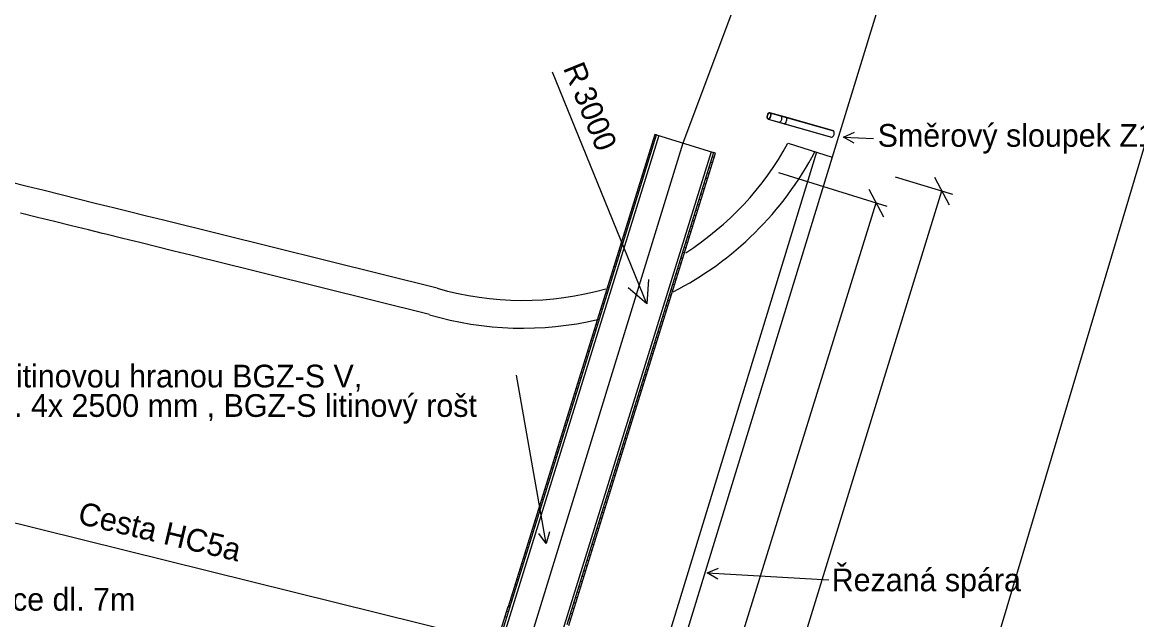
# Model space of a CAD drawing. Extents: x -577013.5 to -576971.5, y -1164310.3 to -1164280.6.
# Drawn here: x -576998.03 to -576987.9, y -1164293.5 to -1164288.07 of the extents above; entities that cross this region are included whole.
import ezdxf

# ---------------------------------------------------------------- set-up
doc = ezdxf.new("R2010")
doc.units = 0
for name, color, linetype in [('37', 7, 'Continuous'), ('5', 7, 'Continuous'), ('60', 7, 'Continuous'), ('Směrové sloupky detail', 7, 'Continuous'), ('Vrstva 1', 7, 'Continuous'), ('Žlab', 7, 'Continuous')]:
    doc.layers.add(name, color=color, linetype=linetype)

msp = doc.modelspace()

# ---------------------------------------------------------------- linework, layer by layer
for p, q in [((-576992.351, -1164290.63), (-576993.207, -1164288.52)), ((-576991.067, -1164289.167), (-576990.666, -1164289.295)), ((-576997.983, -1164289.561), (-576998.138, -1164289.523)), ((-576991.154, -1164289.435), (-576990.17, -1164289.74)), ((-576990.092, -1164289.472), (-576989.572, -1164289.632)), ((-576989.734, -1164289.477), (-576989.602, -1164289.727)), ((-576997.828, -1164289.599), (-576997.983, -1164289.561)), ((-576997.673, -1164289.638), (-576997.828, -1164289.599)), ((-576992.94, -1164300.242), (-576989.668, -1164289.602)), ((-576990.331, -1164289.585), (-576990.199, -1164289.836)), ((-576997.519, -1164289.676), (-576997.673, -1164289.638)), ((-576997.364, -1164289.715), (-576997.519, -1164289.676)), ((-576997.238, -1164289.746), (-576997.364, -1164289.715)), ((-576993.228, -1164299.263), (-576990.265, -1164289.711)), ((-576997.888, -1164289.842), (-576998.043, -1164289.804)), ((-576997.209, -1164289.753), (-576997.238, -1164289.746)), ((-576997.054, -1164289.791), (-576997.209, -1164289.753)), ((-576996.899, -1164289.83), (-576997.054, -1164289.791)), ((-576996.744, -1164289.868), (-576996.899, -1164289.83)), ((-576997.733, -1164289.88), (-576997.888, -1164289.842)), ((-576997.579, -1164289.919), (-576997.733, -1164289.88)), ((-576997.424, -1164289.957), (-576997.579, -1164289.919)), ((-576994.255, -1164290.486), (-576996.744, -1164289.868)), ((-576997.298, -1164289.988), (-576997.424, -1164289.957)), ((-576997.269, -1164289.996), (-576997.298, -1164289.988)), ((-576997.114, -1164290.034), (-576997.269, -1164289.996)), ((-576996.959, -1164290.072), (-576997.114, -1164290.034)), ((-576996.804, -1164290.111), (-576996.959, -1164290.072)), ((-576996.65, -1164290.149), (-576996.804, -1164290.111)), ((-576996.495, -1164290.187), (-576996.65, -1164290.149)), ((-576996.34, -1164290.226), (-576996.495, -1164290.187)), ((-576996.327, -1164290.229), (-576996.34, -1164290.226)), ((-576994.326, -1164290.727), (-576996.327, -1164290.229))]:
    msp.add_line(p, q)
msp.add_lwpolyline([(-576992.334, -1164290.407), (-576992.351, -1164290.63), (-576992.519, -1164290.482)])
for radius, start, end in [(2.748, 302.6493, 331.3573), (3, 297.1177, 332.2826), (2.748, 253.5888, 285.9607), (3, 253.5888, 283.1274)]:
    msp.add_arc((-576993.479, -1164287.85), radius, start, end)
at = {"layer": '37'}
for p, q in [((-576988.545, -1164282.361), (-576990.666, -1164289.295)), ((-576990.807, -1164289.25), (-576994.063, -1164299.897)), ((-576990.666, -1164289.295), (-576993.922, -1164299.942))]:
    msp.add_line(p, q, dxfattribs=at)
at = {"layer": '5'}
msp.add_line((-576992.135, -1164294.101), (-577005.054, -1164290.899), dxfattribs=at)
at = {"layer": '60'}
msp.add_line((-576989.475, -1164282.361), (-576992.024, -1164289.166), dxfattribs=at)
at = {"layer": 'Směrové sloupky detail'}
for p, q in [((-576991.232, -1164288.891), (-576990.654, -1164289.055)), ((-576991.248, -1164288.948), (-576990.671, -1164289.112))]:
    msp.add_line(p, q, dxfattribs=at)
for points in [[(-576991.131, -1164288.919), (-576991.232, -1164288.891)], [(-576991.232, -1164288.891), (-576991.232, -1164288.891)], [(-576991.248, -1164288.948), (-576991.147, -1164288.977), (-576991.147, -1164288.977)], [(-576991.248, -1164288.948), (-576991.248, -1164288.948)], [(-576991.147, -1164288.977), (-576991.104, -1164288.989)], [(-576991.087, -1164288.932), (-576991.087, -1164288.932), (-576991.131, -1164288.919)], [(-576991.104, -1164288.989), (-576990.671, -1164289.112)], [(-576990.654, -1164289.055), (-576991.087, -1164288.932)]]:
    msp.add_lwpolyline(points, dxfattribs=at)
for centre, start_param, end_param in [((-576991.24, -1164288.919), 0, 3.141593), ((-576991.24, -1164288.919), 3.141603, 6.283175), ((-576991.24, -1164288.919), 3.141603, 6.283175), ((-576991.139, -1164288.948), 3.141603, 6.283185), ((-576991.139, -1164288.948), 3.141603, 6.283175), ((-576991.095, -1164288.961), 3.141603, 6.283175), ((-576991.095, -1164288.961), 3.141593, 6.283175), ((-576990.663, -1164289.084), 3.141593, 6.283185)]:
    msp.add_ellipse(centre, major_axis=(0.0082, 0.0289), ratio=0.5, start_param=start_param, end_param=end_param, dxfattribs=at)
msp.add_ellipse((-576991.24, -1164288.919), major_axis=(0.0082, 0.0289), ratio=0.5, dxfattribs=at)
at = {"layer": 'Vrstva 1'}
for p, q in [((-576992.834, -1164306.008), (-576986.608, -1164285.099)), ((-576990.564, -1164289.113), (-576990.289, -1164289.125)), ((-576993.266, -1164292.809), (-576993.534, -1164291.278)), ((-576991.803, -1164293.077), (-576990.697, -1164293.139))]:
    msp.add_line(p, q, dxfattribs=at)
for points in [[(-576990.467, -1164289.167), (-576990.564, -1164289.113), (-576990.462, -1164289.067)], [(-576993.234, -1164292.702), (-576993.266, -1164292.809), (-576993.332, -1164292.719)], [(-576991.706, -1164293.132), (-576991.803, -1164293.077), (-576991.7, -1164293.033)]]:
    msp.add_lwpolyline(points, dxfattribs=at)
at = {"layer": 'Žlab'}
for p, q in [((-576992.242, -1164289.098), (-576995.204, -1164298.649)), ((-576992.279, -1164289.087), (-576992.279, -1164289.087)), ((-576992.263, -1164289.092), (-576991.744, -1164289.253)), ((-576992.024, -1164289.166), (-576994.962, -1164298.726)), ((-576992.306, -1164289.174), (-576992.289, -1164289.177)), ((-576992.291, -1164289.126), (-576992.274, -1164289.129)), ((-576991.764, -1164289.246), (-576994.727, -1164298.797)), ((-576992.351, -1164289.319), (-576992.334, -1164289.322)), ((-576992.336, -1164289.271), (-576992.319, -1164289.274)), ((-576992.321, -1164289.223), (-576992.304, -1164289.225)), ((-576991.756, -1164289.292), (-576991.738, -1164289.294)), ((-576991.744, -1164289.253), (-576991.744, -1164289.253)), ((-576992.381, -1164289.416), (-576992.364, -1164289.418)), ((-576992.366, -1164289.367), (-576992.349, -1164289.37)), ((-576991.786, -1164289.388), (-576991.768, -1164289.391)), ((-576991.771, -1164289.34), (-576991.753, -1164289.343)), ((-576992.411, -1164289.512), (-576992.394, -1164289.515)), ((-576992.396, -1164289.464), (-576992.379, -1164289.467)), ((-576991.815, -1164289.485), (-576991.798, -1164289.487)), ((-576991.801, -1164289.436), (-576991.783, -1164289.439)), ((-576992.441, -1164289.609), (-576992.424, -1164289.611)), ((-576992.426, -1164289.56), (-576992.409, -1164289.563)), ((-576991.845, -1164289.581), (-576991.828, -1164289.584)), ((-576991.83, -1164289.533), (-576991.813, -1164289.536)), ((-576992.471, -1164289.705), (-576992.454, -1164289.708)), ((-576992.456, -1164289.657), (-576992.439, -1164289.66)), ((-576991.89, -1164289.726), (-576991.873, -1164289.729)), ((-576991.875, -1164289.678), (-576991.858, -1164289.68)), ((-576991.86, -1164289.629), (-576991.843, -1164289.632)), ((-576992.501, -1164289.802), (-576992.484, -1164289.804)), ((-576992.486, -1164289.754), (-576992.469, -1164289.756)), ((-576991.92, -1164289.822), (-576991.903, -1164289.825)), ((-576991.905, -1164289.774), (-576991.888, -1164289.777)), ((-576992.531, -1164289.898), (-576992.514, -1164289.901)), ((-576992.516, -1164289.85), (-576992.499, -1164289.853)), ((-576991.95, -1164289.919), (-576991.933, -1164289.922)), ((-576991.935, -1164289.871), (-576991.918, -1164289.873)), ((-576992.561, -1164289.995), (-576992.544, -1164289.998)), ((-576992.546, -1164289.947), (-576992.529, -1164289.949)), ((-576991.98, -1164290.016), (-576991.963, -1164290.018)), ((-576991.965, -1164289.967), (-576991.948, -1164289.97)), ((-576992.591, -1164290.091), (-576992.574, -1164290.094)), ((-576992.576, -1164290.043), (-576992.559, -1164290.046)), ((-576992.01, -1164290.112), (-576991.993, -1164290.115)), ((-576991.995, -1164290.064), (-576991.978, -1164290.067)), ((-576992.621, -1164290.188), (-576992.603, -1164290.191)), ((-576992.606, -1164290.14), (-576992.589, -1164290.142)), ((-576992.04, -1164290.209), (-576992.023, -1164290.211)), ((-576992.025, -1164290.16), (-576992.008, -1164290.163)), ((-576992.666, -1164290.333), (-576992.648, -1164290.335)), ((-576992.651, -1164290.284), (-576992.633, -1164290.287)), ((-576992.636, -1164290.236), (-576992.618, -1164290.239)), ((-576992.07, -1164290.305), (-576992.053, -1164290.308)), ((-576992.055, -1164290.257), (-576992.038, -1164290.26)), ((-576992.696, -1164290.429), (-576992.678, -1164290.432)), ((-576992.681, -1164290.381), (-576992.663, -1164290.384)), ((-576992.1, -1164290.402), (-576992.083, -1164290.404)), ((-576992.085, -1164290.353), (-576992.068, -1164290.356)), ((-576992.726, -1164290.526), (-576992.708, -1164290.529)), ((-576992.711, -1164290.478), (-576992.693, -1164290.48)), ((-576992.13, -1164290.498), (-576992.112, -1164290.501)), ((-576992.115, -1164290.45), (-576992.098, -1164290.453)), ((-576992.756, -1164290.622), (-576992.738, -1164290.625)), ((-576992.741, -1164290.574), (-576992.723, -1164290.577)), ((-576992.16, -1164290.595), (-576992.142, -1164290.597)), ((-576992.145, -1164290.547), (-576992.127, -1164290.549)), ((-576992.786, -1164290.719), (-576992.768, -1164290.722)), ((-576992.771, -1164290.671), (-576992.753, -1164290.673)), ((-576992.205, -1164290.74), (-576992.187, -1164290.742)), ((-576992.19, -1164290.691), (-576992.172, -1164290.694)), ((-576992.175, -1164290.643), (-576992.157, -1164290.646)), ((-576992.815, -1164290.815), (-576992.798, -1164290.818)), ((-576992.801, -1164290.767), (-576992.783, -1164290.77)), ((-576992.235, -1164290.836), (-576992.217, -1164290.839)), ((-576992.22, -1164290.788), (-576992.202, -1164290.791)), ((-576992.845, -1164290.912), (-576992.828, -1164290.915)), ((-576992.83, -1164290.864), (-576992.813, -1164290.866)), ((-576992.265, -1164290.933), (-576992.247, -1164290.935)), ((-576992.25, -1164290.884), (-576992.232, -1164290.887)), ((-576992.875, -1164291.008), (-576992.858, -1164291.011)), ((-576992.86, -1164290.96), (-576992.843, -1164290.963)), ((-576992.295, -1164291.029), (-576992.277, -1164291.032)), ((-576992.28, -1164290.981), (-576992.262, -1164290.984)), ((-576992.905, -1164291.105), (-576992.888, -1164291.108)), ((-576992.89, -1164291.057), (-576992.873, -1164291.059)), ((-576992.324, -1164291.126), (-576992.307, -1164291.128)), ((-576992.31, -1164291.077), (-576992.292, -1164291.08)), ((-576992.935, -1164291.202), (-576992.918, -1164291.204)), ((-576992.92, -1164291.153), (-576992.903, -1164291.156)), ((-576992.354, -1164291.222), (-576992.337, -1164291.225)), ((-576992.339, -1164291.174), (-576992.322, -1164291.177)), ((-576992.98, -1164291.346), (-576992.963, -1164291.349)), ((-576992.965, -1164291.298), (-576992.948, -1164291.301)), ((-576992.95, -1164291.25), (-576992.933, -1164291.253)), ((-576992.384, -1164291.319), (-576992.367, -1164291.321)), ((-576992.369, -1164291.271), (-576992.352, -1164291.273)), ((-576993.01, -1164291.443), (-576992.993, -1164291.446)), ((-576992.995, -1164291.395), (-576992.978, -1164291.397)), ((-576992.414, -1164291.415), (-576992.397, -1164291.418)), ((-576992.399, -1164291.367), (-576992.382, -1164291.37)), ((-576993.04, -1164291.539), (-576993.023, -1164291.542)), ((-576993.025, -1164291.491), (-576993.008, -1164291.494)), ((-576992.444, -1164291.512), (-576992.427, -1164291.515)), ((-576992.429, -1164291.464), (-576992.412, -1164291.466)), ((-576993.07, -1164291.636), (-576993.053, -1164291.639)), ((-576993.055, -1164291.588), (-576993.038, -1164291.59)), ((-576992.474, -1164291.608), (-576992.457, -1164291.611)), ((-576992.459, -1164291.56), (-576992.442, -1164291.563)), ((-576993.1, -1164291.732), (-576993.083, -1164291.735)), ((-576993.085, -1164291.684), (-576993.068, -1164291.687)), ((-576992.519, -1164291.753), (-576992.502, -1164291.756)), ((-576992.504, -1164291.705), (-576992.487, -1164291.708)), ((-576992.489, -1164291.657), (-576992.472, -1164291.659)), ((-576993.13, -1164291.829), (-576993.112, -1164291.832)), ((-576993.115, -1164291.781), (-576993.098, -1164291.783)), ((-576992.549, -1164291.85), (-576992.532, -1164291.852)), ((-576992.534, -1164291.801), (-576992.517, -1164291.804)), ((-576993.16, -1164291.926), (-576993.142, -1164291.928)), ((-576993.145, -1164291.877), (-576993.127, -1164291.88)), ((-576992.579, -1164291.946), (-576992.562, -1164291.949)), ((-576992.564, -1164291.898), (-576992.547, -1164291.901)), ((-576993.19, -1164292.022), (-576993.172, -1164292.025)), ((-576993.175, -1164291.974), (-576993.157, -1164291.977)), ((-576992.609, -1164292.043), (-576992.592, -1164292.045)), ((-576992.594, -1164291.995), (-576992.577, -1164291.997)), ((-576993.22, -1164292.119), (-576993.202, -1164292.121)), ((-576993.205, -1164292.07), (-576993.187, -1164292.073)), ((-576992.639, -1164292.139), (-576992.622, -1164292.142)), ((-576992.624, -1164292.091), (-576992.607, -1164292.094)), ((-576993.25, -1164292.215), (-576993.232, -1164292.218)), ((-576993.235, -1164292.167), (-576993.217, -1164292.17)), ((-576992.669, -1164292.236), (-576992.651, -1164292.239)), ((-576992.654, -1164292.188), (-576992.636, -1164292.19)), ((-576993.295, -1164292.36), (-576993.277, -1164292.363)), ((-576993.28, -1164292.312), (-576993.262, -1164292.314)), ((-576993.265, -1164292.263), (-576993.247, -1164292.266)), ((-576992.699, -1164292.332), (-576992.681, -1164292.335)), ((-576992.684, -1164292.284), (-576992.666, -1164292.287)), ((-576993.324, -1164292.457), (-576993.307, -1164292.459)), ((-576993.31, -1164292.408), (-576993.292, -1164292.411)), ((-576992.729, -1164292.429), (-576992.711, -1164292.432)), ((-576992.714, -1164292.381), (-576992.696, -1164292.383)), ((-576993.354, -1164292.553), (-576993.337, -1164292.556)), ((-576993.339, -1164292.505), (-576993.322, -1164292.507)), ((-576992.759, -1164292.525), (-576992.741, -1164292.528)), ((-576992.744, -1164292.477), (-576992.726, -1164292.48)), ((-576993.384, -1164292.65), (-576993.367, -1164292.652)), ((-576993.369, -1164292.601), (-576993.352, -1164292.604)), ((-576992.789, -1164292.622), (-576992.771, -1164292.625)), ((-576992.774, -1164292.574), (-576992.756, -1164292.576)), ((-576993.414, -1164292.746), (-576993.397, -1164292.749)), ((-576993.399, -1164292.698), (-576993.382, -1164292.701)), ((-576992.834, -1164292.767), (-576992.816, -1164292.77)), ((-576992.819, -1164292.719), (-576992.801, -1164292.721)), ((-576992.804, -1164292.67), (-576992.786, -1164292.673)), ((-576993.444, -1164292.843), (-576993.427, -1164292.845)), ((-576993.429, -1164292.794), (-576993.412, -1164292.797)), ((-576992.863, -1164292.863), (-576992.846, -1164292.866)), ((-576992.848, -1164292.815), (-576992.831, -1164292.818)), ((-576993.474, -1164292.939), (-576993.457, -1164292.942)), ((-576993.459, -1164292.891), (-576993.442, -1164292.894)), ((-576992.893, -1164292.96), (-576992.876, -1164292.963)), ((-576992.878, -1164292.912), (-576992.861, -1164292.914)), ((-576993.504, -1164293.036), (-576993.487, -1164293.038)), ((-576993.489, -1164292.987), (-576993.472, -1164292.99)), ((-576992.923, -1164293.056), (-576992.906, -1164293.059)), ((-576992.908, -1164293.008), (-576992.891, -1164293.011)), ((-576993.534, -1164293.132), (-576993.517, -1164293.135)), ((-576993.519, -1164293.084), (-576993.502, -1164293.087)), ((-576992.953, -1164293.153), (-576992.936, -1164293.156)), ((-576992.938, -1164293.105), (-576992.921, -1164293.107)), ((-576993.564, -1164293.229), (-576993.547, -1164293.231)), ((-576993.549, -1164293.181), (-576993.532, -1164293.183)), ((-576992.983, -1164293.249), (-576992.966, -1164293.252)), ((-576992.968, -1164293.201), (-576992.951, -1164293.204)), ((-576993.609, -1164293.374), (-576993.592, -1164293.376)), ((-576993.594, -1164293.325), (-576993.577, -1164293.328)), ((-576993.579, -1164293.277), (-576993.562, -1164293.28)), ((-576993.013, -1164293.346), (-576992.996, -1164293.349)), ((-576992.998, -1164293.298), (-576992.981, -1164293.3)), ((-576993.64, -1164293.472), (-576993.622, -1164293.475)), ((-576993.625, -1164293.424), (-576993.607, -1164293.427)), ((-576993.613, -1164293.385), (-576993.613, -1164293.385)), ((-576993.612, -1164293.385), (-576993.596, -1164293.39)), ((-576993.043, -1164293.443), (-576993.026, -1164293.445)), ((-576993.028, -1164293.394), (-576993.011, -1164293.397)), ((-576993.058, -1164293.491), (-576993.041, -1164293.494))]:
    msp.add_line(p, q, dxfattribs=at)
for points in [[(-576992.279, -1164289.087), (-576992.279, -1164289.087), (-576993.612, -1164293.385)], [(-576993.596, -1164293.39), (-576993.003, -1164291.48), (-576992.263, -1164289.092), (-576992.279, -1164289.087)], [(-576991.744, -1164289.253), (-576991.744, -1164289.253), (-576993.076, -1164293.55)], [(-576993.06, -1164293.555), (-576992.467, -1164291.645), (-576991.727, -1164289.257), (-576991.744, -1164289.253)], [(-576993.613, -1164293.385), (-576993.613, -1164293.385), (-576994.945, -1164297.683)], [(-576994.929, -1164297.688), (-576994.336, -1164295.778), (-576993.596, -1164293.39), (-576993.613, -1164293.385)]]:
    msp.add_lwpolyline(points, dxfattribs=at)

# ---------------------------------------------------------------- texts
for s, p in [('R', (-576993.114, -1164288.483)), ('3000', (-576993.024, -1164288.705))]:
    msp.add_text(s, height=0.2, rotation=292.0741).set_placement(p)
at = {"layer": 'Vrstva 1'}
for s, p in [('Směrový sloupek Z11g', (-576990.252, -1164289.2)), ('Žlab se zabudovanou litinovou hranou BGZ-S V,', (-577000.866, -1164291.389)), ('světlá šířka NW 500 dl. 4x 2500 mm , BGZ-S litinový rošt', (-577000.866, -1164291.657)), ('Řezaná spára', (-576990.67, -1164293.243)), ('Ocelová svodnice dl. 7m', (-577000.01, -1164293.42))]:
    msp.add_text(s, height=0.20663, dxfattribs=at).set_placement(p)
msp.add_text('Cesta HC5a', height=0.2066, rotation=346.6454, dxfattribs=at).set_placement((-576997.533, -1164292.626))

doc.saveas('drawing.dxf')
